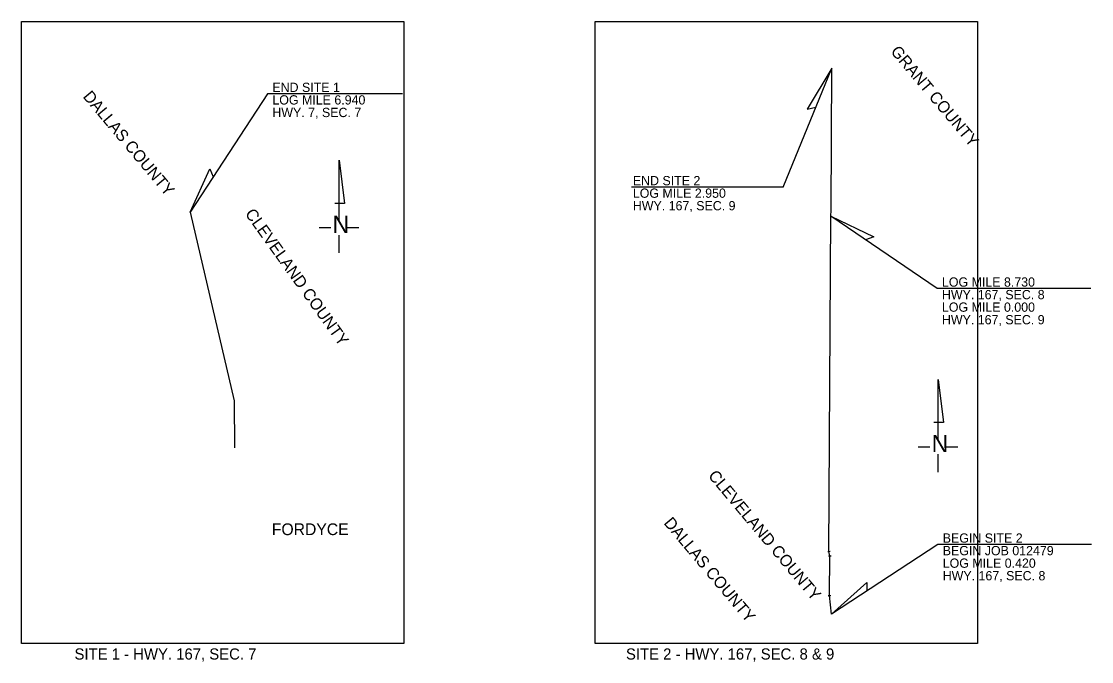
# Model space of a CAD drawing. Extents: x 10700 to 22009, y 10612 to 15552.
# Drawn here: x 10958 to 13844, y 10612 to 12339 of the extents above; entities that cross this region are included whole.
import ezdxf

# ---------------------------------------------------------------- set-up
doc = ezdxf.new("R2010")
doc.units = 0
for name, color, linetype in [('30', 7, 'Continuous'), ('6', 7, 'Continuous'), ('Default', 7, 'Continuous'), ('R_Dimension', 7, 'Continuous'), ('R_Draft', 7, 'Continuous'), ('R_No Plot', 7, 'Continuous')]:
    doc.layers.add(name, color=color, linetype=linetype)

msp = doc.modelspace()

# ---------------------------------------------------------------- linework, layer by layer
at = {"layer": 'Default'}
msp.add_lwpolyline([(11412.5, 11824.8), (11531.3, 11316), (11532, 11188.8)], dxfattribs=at)
at = {"layer": 'R_Dimension'}
for p, q in [((11985.1, 12143.7), (11621.2, 12143.7)), ((13012.2, 11892), (12603, 11892)), ((13841.6, 11618.4), (13427.1, 11618.4)), ((13843.7, 10927.7), (13429.1, 10927.7))]:
    msp.add_line(p, q, dxfattribs=at)
for points in [[(13012.2, 11892), (13142.7, 12213.4), (13076.9, 12102.9), (13099.8, 12107.9)], [(11621.2, 12143.7), (11412.5, 11824.8), (11465.9, 11941.8), (11474.9, 11920.1)], [(13427.1, 11618.4), (13140.2, 11813.9), (13256.1, 11758.4), (13234.3, 11749.8)], [(13429.1, 10927.7), (13142.2, 10739.7), (13237.9, 10825.6), (13237.5, 10802.1)]]:
    msp.add_lwpolyline(points, dxfattribs=at)
at = {"layer": 'R_Draft'}
for p, q in [((11814.2, 11964.8), (11828.8, 11848.4)), ((11814.2, 11802.1), (11814.2, 11964.8)), ((11802.9, 11849.3), (11828.8, 11849.3)), ((11760.7, 11782.9), (11791.6, 11782.9)), ((11834.8, 11782.9), (11867.7, 11782.9)), ((11814.2, 11714.8), (11814.2, 11762.6)), ((13429.8, 11373.5), (13444.4, 11257.1)), ((13429.8, 11210.8), (13429.8, 11373.5)), ((13418.6, 11258), (13444.4, 11258)), ((13376.3, 11191.6), (13407.2, 11191.6)), ((13429.8, 11123.5), (13429.8, 11171.4)), ((13450.4, 11191.6), (13483.3, 11191.6))]:
    msp.add_line(p, q, dxfattribs=at)
at = {"layer": 'R_No Plot'}
for p, q in [((13132, 10909.1), (13138.5, 10909.9)), ((13134.4, 10897.1), (13140.9, 10897.8)), ((13133.5, 10790.4), (13140, 10790.8))]:
    msp.add_line(p, q, dxfattribs=at)
for points in [[(10957.5, 12339.4), (11988.9, 12339.4), (11988.9, 10661.4), (10957.5, 10661.4)], [(12504.6, 12339.4), (13535.9, 12339.4), (13535.9, 10661.4), (12504.6, 10661.4)]]:
    msp.add_lwpolyline(points, close=True, dxfattribs=at)
msp.add_lwpolyline([(13142.2, 10739.7), (13136.8, 10790.6), (13137.7, 10897.5), (13135.3, 10909.5), (13140.2, 11813.9), (13141.1, 11829.9), (13142.7, 12213.4)], dxfattribs=at)

# ---------------------------------------------------------------- texts
at = {"layer": '30'}
for s, rotation, p in [('GRANT COUNTY', 310, (13299.9, 12257.4)), ('DALLAS COUNTY', 310, (11121.8, 12135.8)), ('CLEVELAND COUNTY', 305.6244, (11559.2, 11820.3)), ('CLEVELAND COUNTY', 310, (12807.9, 11112.6)), ('DALLAS COUNTY', 310, (12688.3, 10985.3))]:
    msp.add_text(s, height=31.68, rotation=rotation, dxfattribs=at).set_placement(p)
at = {"layer": '6'}
msp.add_text('FORDYCE', height=31.68, dxfattribs=at).set_placement((11632.9, 10953.4))
at = {"layer": 'R_Dimension'}
for s, height, rotation, p in [('END SITE 1', 25, 359.9994, (11634.3, 12149)), ('LOG MILE 6.940', 25, 359.9994, (11634.3, 12115.1)), ('HWY. 7, SEC. 7', 25, 359.9994, (11634.3, 12081.2)), ('END SITE 2', 25, 359.9994, (12606.5, 11897.3)), ('LOG MILE 2.950', 25, 359.9994, (12606.5, 11863.5)), ('HWY. 167, SEC. 9', 25, 359.9994, (12606.5, 11829.6)), ('LOG MILE 8.730', 25, 359.9999, (13440.1, 11623.7)), ('HWY. 167, SEC. 8', 25, 359.9999, (13440.1, 11589.8)), ('LOG MILE 0.000', 25, 359.9999, (13440.1, 11556)), ('HWY. 167, SEC. 9', 25, 359.9999, (13440.1, 11522.1)), ('BEGIN SITE 2', 25, 359.9999, (13442.2, 10933)), ('BEGIN JOB 012479', 25, 359.9999, (13442.2, 10899.1)), ('LOG MILE 0.420', 25, 359.9999, (13442.2, 10865.3)), ('HWY. 167, SEC. 8', 25, 359.9999, (13442.2, 10831.4)), ('SITE 1 - HWY. 167, SEC. 7', 30, 359.9999, (11100.8, 10617.7)), ('SITE 2 - HWY. 167, SEC. 8 & 9', 30, 359.9999, (12587.9, 10617.7))]:
    msp.add_text(s, height=height, rotation=rotation, dxfattribs=at).set_placement(p)
at = {"layer": 'R_Draft'}
for p in [(11796.6, 11768.5), (13412.2, 11177.3)]:
    msp.add_text('N', height=46.5, dxfattribs=at).set_placement(p)

doc.saveas('drawing.dxf')
